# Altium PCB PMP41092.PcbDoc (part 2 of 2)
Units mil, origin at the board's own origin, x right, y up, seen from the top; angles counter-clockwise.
Board outline 1771.65 x 1771.65 mil, 6 copper layers (Top Layer 1, Layer 2, Layer 3, Layer 4, Layer 5, Bottom Layer), stack 32.112 mil thick; 119 components, 63 nets, 374 pads, 304 vias.
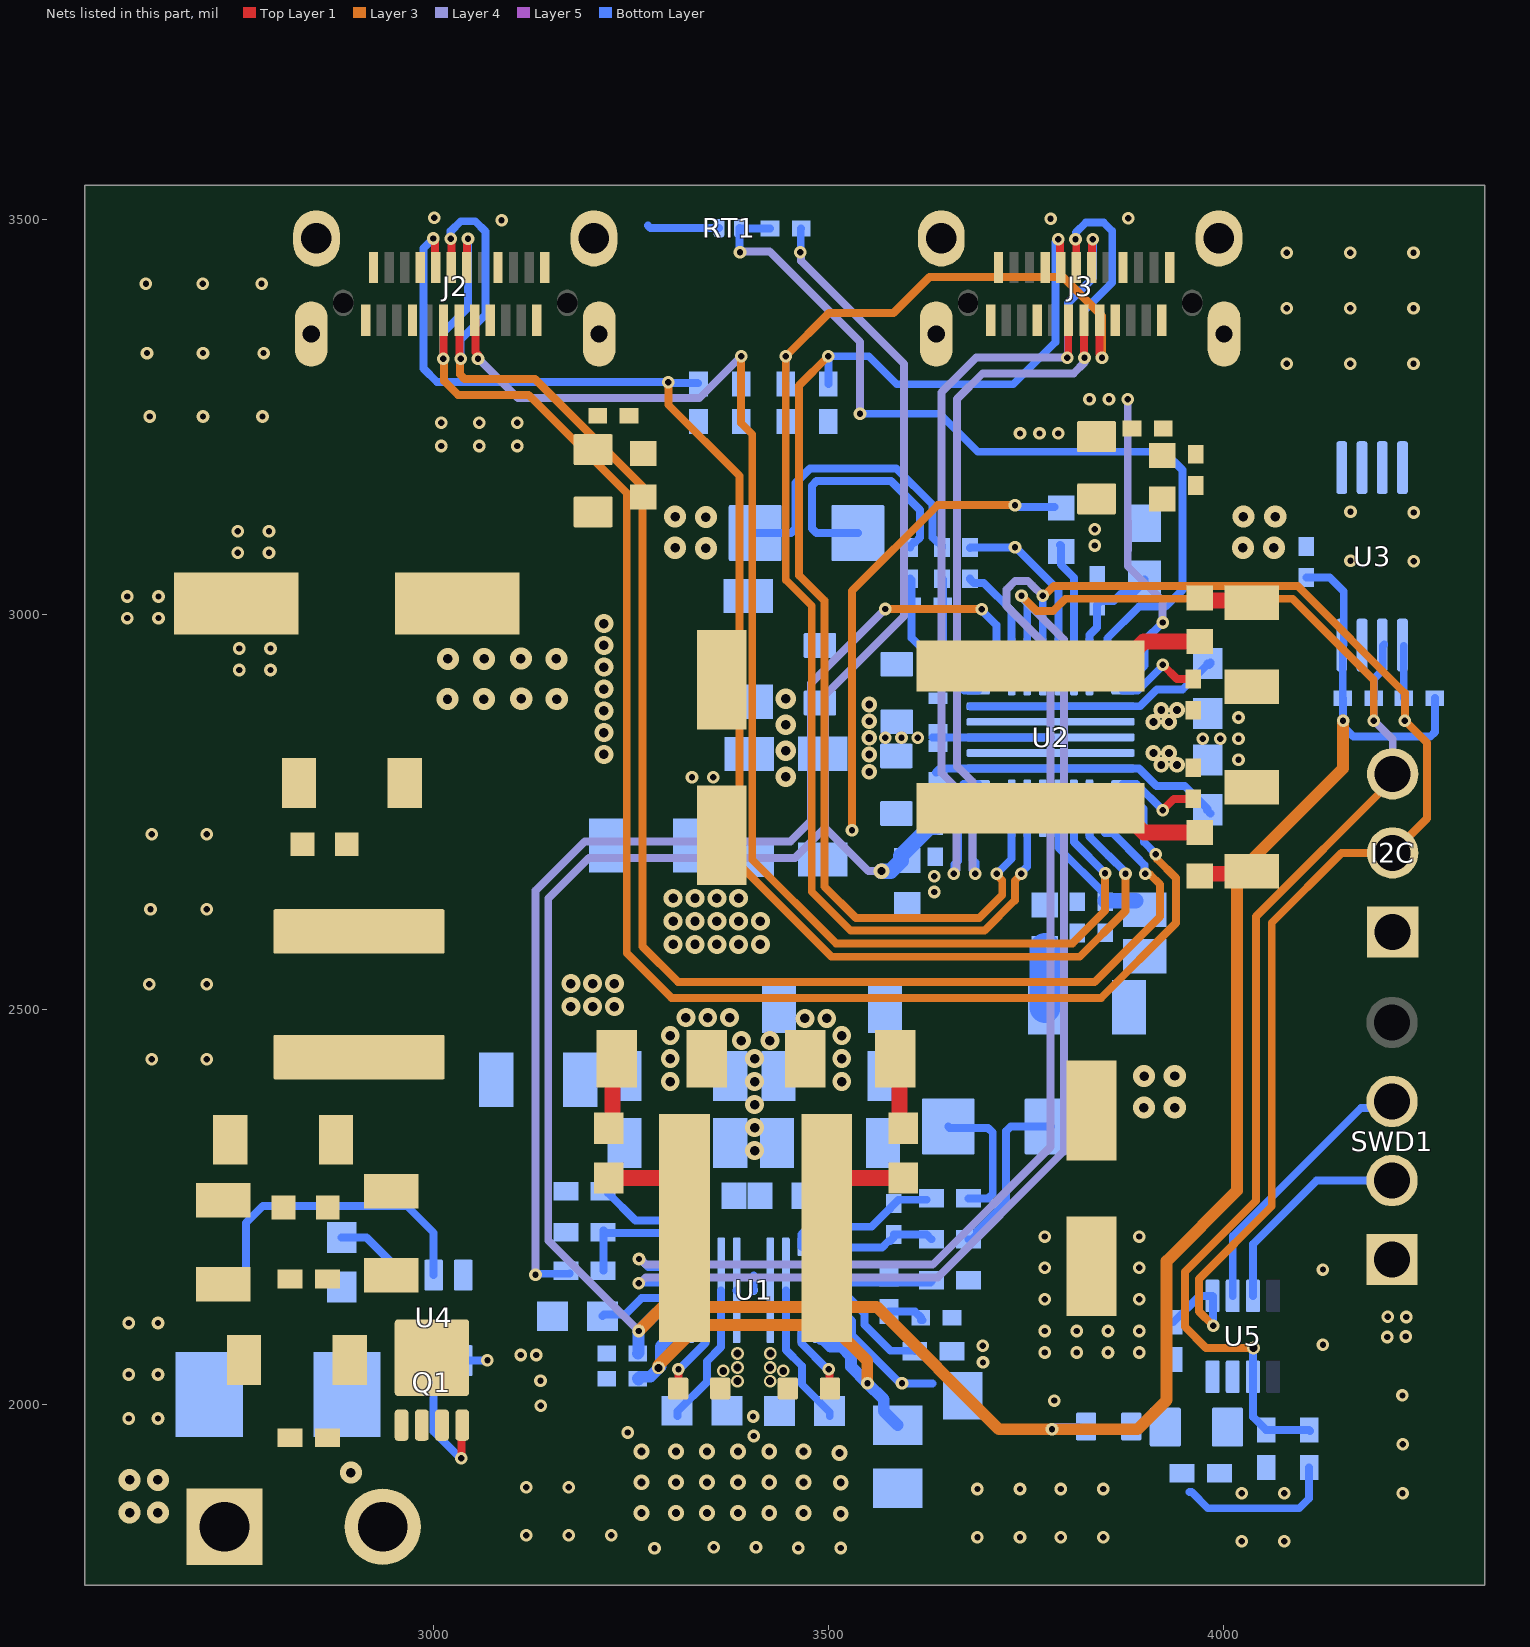
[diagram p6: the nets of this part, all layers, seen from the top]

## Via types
v1: diameter 16, hole 8, Top Layer 1 to Bottom Layer, tented top, 181 vias
v2: diameter 24, hole 12, Top Layer 1 to Bottom Layer, tented top, 45 vias
v3: diameter 20, hole 10, Top Layer 1 to Bottom Layer, tented top, 34 vias
v4: diameter 28, hole 12, Top Layer 1 to Bottom Layer, 25 vias
v5: diameter 16, hole 10, Top Layer 1 to Bottom Layer, tented top, 8 vias
v6: diameter 16, hole 8, Top Layer 1 to Bottom Layer, tented both sides, 4 vias
v7: diameter 26, hole 12, Top Layer 1 to Bottom Layer, tented top, 4 vias
v8: diameter 16, hole 10, Top Layer 1 to Bottom Layer, tented both sides, 2 vias
v9: diameter 20, hole 10, Top Layer 1 to Bottom Layer, tented both sides, 1 vias

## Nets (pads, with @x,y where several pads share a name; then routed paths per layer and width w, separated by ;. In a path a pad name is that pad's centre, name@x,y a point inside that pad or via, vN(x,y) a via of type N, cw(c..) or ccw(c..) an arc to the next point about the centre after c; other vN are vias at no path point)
3V3_MCU: C20.1 C27.2 R11.2 R12.2 R13.2 U5.4 | length 204.3
  Bottom Layer w10: 3956.99,1889.99 3959.39,1889.99 3980.14,1869.24 4095.86,1869.24 4108.41,1881.79 R13.2@4108.41,1920.9
AGND: C30.2 C31.2 C32.2 NT1.1 R7.1 R8.2 R9.1 U1.17 | length 179.2
  Bottom Layer w10: U1.17@3499.81,2115.44 3499.89,2115.36 3520.64,2115.36 3529.81,2106.19 3529.81,2088.19 3587.47,2030.53 3588.57,2030.53 3592.19,2026.91 3631.76,2026.91
  other v1: 3593.2,2027.53 3695.62,2053.72 3110.76,2063.14 3130.55,2063.14 3695.57,2074.82
AGND1: C59.2 C60.2 C63.2 C64.2 NT2.2 R22.1 U2.5 | length 231.5
  Bottom Layer w10: R22.1@3679.22,3084.24 3679.89,3084.91 3736.7,3084.91 3736.92,3085.12 3791.04,3031 U2.5@3791.04,2934.08
  other v1: 3736.1,3085.12 3837,3087.39 3837,3108
  other v6: 3634,2649 3634,2669
BATGND: C1.2 C2.2 C71.2 D1.1 J1.1 L4.1 U4.2 | length 377.9
  Bottom Layer w10: 2763.51,2166.67 2763.04,2167.14 2763.04,2230.18 2784.66,2251.8 2966.54,2251.8 3000.68,2217.66 U4.2@3000.68,2164.2
  other v1: 2614.89,1982.83 2651.86,1982.83 2614.89,2038.52 2651.86,2038.52 2614.89,2103.69 2651.86,2103.69
  other v4: 2615.98,1863.65 2651.81,1863.65 2615.98,1905.06 2651.81,1905.06
BOOT1: C41.1 U2.16 | length 108.8
  Top Layer 1 w10: v1(3923,2752.54) 3937.24,2766.78 C41.1@3961.99,2766.78
  Bottom Layer w10: U2.16@3872.73,2785.46 3872.81,2785.38 3890.16,2785.38 v1(3923,2752.54)
BOOT2: C42.1 U2.10 | length 112.4
  Top Layer 1 w10: v1(3923,2936.49) 3941.11,2918.38 C42.1@3961.99,2918.38 ; C42.1@3958.97,2920.36 C42.1@3959.82,2919.51
  Bottom Layer w10: U2.10@3872.73,2903.57 3872.81,2903.65 3891.54,2903.65 3923,2935.1 v1(3923,2936.49)
COMP: C31.1 R10.2 U1.15 | length 130
  Bottom Layer w10: U1.15@3499.81,2154.81 R10.2@3575.55,2154.81 ; R10.2@3576.64,2154.81 3629.03,2154.81 C31.1@3630.35,2156.13
EN_UVLO: R16.1 U2.6 | length 161.3
  Bottom Layer w10: R16.1@3793.32,3088.06 3794.16,3087.22 3794.16,3063.17 3810.8,3046.53 3810.8,2934.16 U2.6@3810.73,2934.08
FSW: R7.2 U1.6 | length 158.9
  Bottom Layer w10: R7.2@3220.96,2268.33 3256.05,2233.25 3323.34,2233.25 3344.7,2211.89 U1.6@3344.7,2200.08
GND: C3.2 C4.2 C5.2 C6.2 C7.2 C8.2 C9.2 C10.2 C11.2 C16.2 C17.2 C18.2 C19.2 C20.2 C21.2 C22.2 C23.2 C24.2 C25.2 C26.2 C27.1 C28.2 C35.2 C36.1 C37.2 C38.2 C39.1 C40.2 C43.2 C44.2 C47.2 C48.1 C50.1 C51.2 C53.1 C54.2 C55.1 C58.1 C61.2 C62.2 C65.1 C66.2 C67.2 C68.2 C69.2 I2C.1 J2.A1 J2.A12 J2.B1 J2.B12 J2.Shell J3.A1 J3.A12 J3.B1 J3.B12 J3.Shell L4.2 NT1.2 NT2.1 R1.2 R2.2 R15.1 R17.2 R23.1 RT1.1 SWD1.1 U1.9 U2.13 U3.1 U3.2 U3.3 U3.4 U3.7 U5.3 | length 259.6
  Bottom Layer w10: 3271.65,3492.13 3274.84,3488.94 RT1.1@3361.77,3488.94 ; U1.9@3405.69,2144.97 3405.69,2163.96 ; 3631.99,2844.51 U2.13@3781.2,2844.51
  other v1: 3279.99,1818.73 3461.97,1818.9 3515.75,1818.9 3355.02,1819.72 3408.44,1819.72 4022.88,1827.45 4076.66,1827.45 3688.64,1832.69 3742.43,1832.69 3793.96,1832.69 3847.74,1832.69 3117.77,1835.15 3171.55,1835.15 3225.33,1835.15 4022.88,1888.24 4076.66,1888.24 4226.58,1888.17 3688.64,1893.49 3742.43,1893.49 3793.96,1893.49 3847.74,1893.49 3117.77,1895.95 3171.55,1895.95 4226.75,1950.07 3405.51,1960.63 3246.22,1965.03 3404.79,1985.32 3136.21,1998.96 3785.8,2005.44 4226.38,2011.96 3135.91,2030.52 3773.86,2066.27 3814.13,2066.27 3853.83,2066.27 3893.24,2066.27 4125.79,2076.27 4207.31,2085.81 4230.57,2086.44 3773.86,2093.56 3814.13,2093.56 3853.83,2093.56 3893.24,2093.56 4231.12,2111.15 4207.7,2111.53 3773.86,2133.83 3893.24,2133.83 4125.79,2171.18 3773.86,2173.53 3893.24,2173.53 3773.86,2212.94 3893.24,2212.94 2643.78,2437.17 2713.45,2437.17 2640.81,2532.09 2713.45,2532.09 2642.29,2627 2713.45,2627 2643.78,2721.91 2713.45,2721.91 3327.54,2794.18 3354.59,2794.29 4019,2816.26 3973.67,2842.74 3996,2843 4019,2843 3572.16,2844 3592.58,2844 3613,2844 4019,2869.74 2754.82,2929.75 2794.24,2929.75 2754.82,2957.04 2794.24,2957.04 2613.02,2995.5 2652.44,2995.5 2613.02,3022.79 2652.44,3022.79 4240.83,3067.22 4160.67,3068.12 2752.94,3078.13 2792.36,3078.13 2752.94,3105.42 2792.36,3105.42 4240.83,3129.12 4160.67,3130.01 2641.6,3250.64 2708.87,3250.64 2784.03,3250.64 4080.11,3317.35 4160.27,3317.35 4240.43,3317.35 2638.02,3330.8 2708.88,3330.8 2785.46,3330.8 4080.11,3387.59 4160.27,3387.59 4240.43,3387.59 2636.57,3418.44 2708.66,3418.44 2782.93,3418.44 4080.11,3457.84 4160.27,3457.84
  other v2: 3406.75,2321.78 3406.75,2350.88 3406.75,2379.99 3300,2409.09 3406.75,2409.09 3517,2409.09 3300,2438.2 3406.75,2438.2 3517,2438.2 3390,2461 3426,2461 3300,2467.3 3517,2467.3 3470.44,2489 3498,2489 3319.87,2490 3347.44,2490 3375,2490 3174.31,2503.89 3201.87,2503.89 3229.44,2503.89 3174.31,2533 3201.87,2533 3229.44,2533 3303.75,2582.79 3331.31,2582.79 3358.87,2582.79 3386.44,2582.79 3414,2582.79 3303.75,2611.89 3331.31,2611.89 3358.87,2611.89 3386.44,2611.89 3414,2611.89 3303.75,2641 3331.31,2641 3358.87,2641 3386.44,2641 3216,2823.06 3216,2850.62 3216,2878.19 3216,2905.75 3216,2933.31 3216,2960.87 3216,2988.44
  other v3: 3515.75,1862.2 3263.78,1863.03 3307.09,1863.03 3346.46,1863.03 3385.83,1863.03 3425.2,1863.03 3468.5,1863.03 3263.78,1901.99 3307.09,1901.99 3346.46,1901.99 3385.83,1901.99 3425.2,1901.99 3468.5,1901.99 3515.75,1901.57 3514.04,1939.26 3263.78,1940.94 3307.09,1940.94 3346.46,1940.94 3385.83,1940.94 3425.2,1940.94 3468.5,1940.94 3551.74,2801 3551.74,2823 3551.74,2844 3551.74,2865 3551.74,2886
  other v6: 4240.43,3457.84
  other v7: 3446.26,2794.76 3446.26,2827.74 3446.26,2860.71 3446.26,2893.68
I2C1_SCL: C35.1 I2C.3 R13.1 R25.1 U1.3 U2.3 U3.6 U5.2 | length 3286.2
  Layer 3 w10: v1(3744.46,3023.61) 3763.49,3004.61 3784.61,3004.61 3800,3020 4087.37,3020 4190.11,2917.27 v1(4190.11,2865.79) ; v8(4038,2072) 3978,2072 3951.14,2098.86 3951.14,2168.4 4041,2258.26 4041,2618 4214,2791 I2C.3@4214,2798.35
  Layer 4 w10: v1(3260.15,2153.76) 3261.35,2153.76 3269.01,2161.42 3638.66,2161.42 3798,2320.75 3798,2968.45 3744.46,3021.99 v1(3744.46,3023.61) ; v1(4190.11,2865.79) 4214.09,2841.8 4214.09,2798.45 I2C.3@4214,2798.35
  Bottom Layer w10: v1(3260.15,2153.76) 3261.12,2154.73 3310.76,2154.73 U1.3@3310.84,2154.81 ; v1@3741.66,3024.79 v1@3742.84,3023.61 ; v1(3744.46,3023.61) v1@3742.84,3023.61 ; U2.3@3751.67,2934.08 3751.67,3014.78 v1@3742.84,3023.61 ; v8(4038,2072) 4037.29,2071.29 U5.2@4037.29,2035.52 4037.29,1984.86 C35.1@4054.01,1968.14 R13.1@4108.41,1968.14 R13.1@4109.45,1967.09 ; v1(4190.11,2865.79) 4190.11,2893.76 R25.1@4190.26,2893.91 4190.26,2918.47 4201.49,2929.7 4201.49,2960.34 U3.6@4203.38,2962.23
I2C1_SDA: I2C.2 R12.1 R26.1 U1.4 U2.4 U3.5 U5.5 | length 3208.9
  Layer 3 w10: v1(3771.36,3023.61) 3772.98,3023.61 3785.37,3036 4094,3036 4229.47,2900.53 v1(4229.47,2865.79) 4257.48,2837.78 4257.48,2741.83 I2C.2@4214,2698.35 4149.35,2698.35 4061,2610 4061,2251.39 3969,2159.39 3969,2118 v1(3987,2100)
  Layer 4 w10: v1(3260.45,2184.51) 3262.07,2184.51 3269.17,2177.42 3632.04,2177.42 3781,2326.38 3781,2955.22 3725.43,3010.79 3725.43,3031.51 3736.56,3042.64 3752.3,3042.64 3758.16,3036.78 v1(3771.36,3023.61) v1@3771.36,3021.97
  Bottom Layer w10: v1(3260.45,2184.51) 3262.07,2184.51 3272.1,2174.49 U1.4@3310.84,2174.49 ; U2.4@3771.36,2934.08 v1@3771.36,3021.97 ; R12.1@3936.37,2104.49 3969.76,2137.88 U5.5@3986.11,2137.88 3986.55,2137.43 3986.55,2100.45 v1(3987,2100) ; U3.5@4228.11,2960.16 R26.1@4228.11,2894.27 4229.47,2892.91 v1(4229.47,2865.79)
IN: C5.1 C6.1 C7.1 L2.2 L6.1 L9.1
  other v4: 3018.17,2893.05 3064.12,2893.05 3111.4,2893.39 3156.32,2893.05 3018.6,2943.92 3064.55,2943.92 3110.96,2944.26 3155.88,2943.92
IRQ1: R22.2 U2.2 | length 140.5
  Bottom Layer w10: R22.2@3679.22,3045.33 3679.22,3044.76 3684.06,3039.92 3696.68,3039.92 3731.99,3004.61 U2.2@3731.99,2934.08
ISN: C29.1 R6.2 U1.13 | length 154.4
  Bottom Layer w10: U1.13@3485.64,2199.1 3568.06,2199.1 3575.95,2206.99 3577.92,2206.99 3582.76,2211.83 C29.1@3582.76,2213.8 ; C29.1@3582.76,2215.48 3624.43,2215.48 R6.2@3630.35,2209.56
ISP: C29.2 R4.2 U1.12 | length 192.3
  Bottom Layer w10: U1.12@3465.96,2200.08 3465.96,2215.55 3475.75,2225.34 3554.57,2225.34 3577.27,2248.04 3577.92,2248.04 3578.34,2248.46 3578.34,2249.11 3588.78,2259.55 R4.2@3624.2,2259.55
LDO_1V5: C63.1 C64.1 U2.7 | length 157.3
  Bottom Layer w10: U2.7@3830.41,2934.08 3830.49,2934.16 3830.49,2973.99 3840,2983.5 C64.1@3840,3010.32 3840,3012.28 3844.84,3017.13 3861.16,3017.13 3869.98,3025.94 3884.33,3025.94 3900,3041.61 C63.1@3900,3044.57
LDO_3V3: C28.1 C59.1 C60.1 C65.2 R11.1 R24.2 R25.2 R26.2 U1.1 U2.27 U3.8 | length 4332.3
  Layer 3 w15: v1(3260.15,2093.49) 3290.66,2124 3561.04,2124 3715.83,1969.21 v1(3782.97,1969.21) 3891.21,1969.21 3928,2006 3928,2182 4017,2271 4017,2671 4151.3,2805.3 v1(4151.3,2865.79)
  Layer 4 w10: v1(3260.15,2093.49) 3145.59,2208.05 3145.59,2640.59 3197,2692 3457.58,2692 3495.78,2730.2 ; v1(3464.51,3458.42) 3465.66,3457.28 3465.66,3447.34 3596,3317 3596,2998 3495.78,2897.78 3495.78,2730.2 ; v9(3567.28,2675.28) 3550.7,2675.28 3495.78,2730.2
  Bottom Layer w10: v1(3464.51,3458.42) 3465.07,3458.98 3465.07,3487.85 R24.2@3465.62,3488.4 ; C59.1@3639.95,2737.84 3639.95,2754.42 3670.91,2785.38 3689.58,2785.38 U2.27@3689.66,2785.46 ; C65.2@4104.8,3046.76 4134.45,3046.76 4152.18,3029.03 4152.18,2962.24 4150.89,2960.92 R25.2@4150.89,2893.91 4151.3,2893.5 v1(4151.3,2865.79) ; 4152.45,2857.41 4164.41,2845.44 4261.62,2845.44 4267.48,2851.3 R26.2@4267.48,2894.27
  Bottom Layer w15: C28.1@3259,2065 3259.96,2065.96 3259.96,2093.3 v1(3260.15,2093.49) ; v1@3261.31,2095.11 3281.64,2115.44 U1.1@3310.84,2115.44 ; v1(3782.97,1969.21) 3783.16,1969.4 3813.43,1969.4 3813.65,1969.62 R11.1@3817.31,1969.62 ; 4151.3,2857.41 v1(4151.3,2865.79)
  Bottom Layer w20: v9(3567.28,2675.28) 3578.72,2675.28 3592,2688.56 3592,2694.8 3628.39,2731.18 3634.95,2731.18 3635.11,2731.34 C59.1@3635.11,2733
LDO_5V: C61.1 C62.1 U2.21 | length 180.1
  Bottom Layer w10: U2.21@3791.04,2754.95 3791.04,2705 3850.39,2645.65 C61.1@3850.39,2637.8
  Bottom Layer w20: C61.1@3850.39,2637.8 C62.1@3888.73,2637.8
MODE: R8.1 U1.2 | length 106.1
  Bottom Layer w10: R8.1@3214.21,2112.29 3216.25,2114.33 3243.04,2114.33 3263.84,2135.12 U1.2@3310.84,2135.12
NetC1_1: C1.1 C2.1 L3.1 Q1.5 Q1.6 Q1.7 Q1.8 Q1.9@2998.45,2059.73 U4.4 | length 39.9
  Top Layer 1 w10: Q1.9@2991.6,2060.29 Q1.9@2998.06,2053.82
  Bottom Layer w10: U4.4@3038.08,2055.93 3038.54,2056.39 v1(3068.67,2056.39)
NetC3_1: C3.1 C4.1 L2.1 L3.2
NetC8_1: C8.1 C9.1 C10.1 C11.1 L6.2 U1.7 | length 182.1
  Bottom Layer w10: C11.1@3309.19,1985.7 3309.19,1991.91 3346.35,2029.07 3346.35,2055.14 3364.3,2073.1 3364.3,2144.89 U1.7@3364.38,2144.97
NetC12_1: C12.1 R1.1 | length 92.2
  Top Layer 1 w20: C12.1@3222,2349.99 3227.1,2355.09 3227.1,2432.9 R1.1@3232.2,2438
NetC12_2: C12.2 C14.2 L7.1 U1.8 | length 146.2
  Top Layer 1 w20: C12.2@3222,2287 3295.95,2287 3318.04,2264.91 L7.1@3318.04,2224
  Bottom Layer w10: U1.8@3383.99,2144.89 U1.8@3384.07,2144.97
  other v5: 3385,2030 3367,2043 3385,2047.28 3385,2065
NetC13_1: C13.1 C15.2 L7.2 U1.10 | length 147.1
  Top Layer 1 w20: L7.2@3497.96,2224 3497.96,2264.91 3520.05,2287 C13.1@3595,2287
  other v5: 3426.3,2030 3443,2043 3426.3,2047.28 3426.6,2065
NetC13_2: C13.2 R2.1 | length 92.2
  Top Layer 1 w20: R2.1@3584.8,2438 3589.9,2432.9 3589.9,2355.09 C13.2@3595,2349.99
NetC14_1: C14.1 U1.20 | length 85
  Top Layer 1 w10: C14.1@3310.01,2020.61 3310.32,2020.93 v1(3310.32,2044.9) v1@3310.95,2045.53
  Bottom Layer w10: v1(3310.32,2044.9) 3311.2,2044.9 3344.7,2078.4 U1.20@3344.7,2089.85
NetC15_1: C15.1 U1.19 | length 86.2
  Top Layer 1 w10: v1(3500.69,2044.9) 3501.32,2044.27 3501.32,2020.13 C15.1@3501.95,2019.5
  Bottom Layer w10: U1.19@3465.96,2089.85 3465.96,2078.04 3499.09,2044.9 v1(3500.69,2044.9)
NetC16_1: C16.1 C17.1 C18.1 C19.1 C44.1 R3.1 R4.1 U1.11 | length 352.1
  Bottom Layer w10: U1.11@3446.27,2144.97 3446.35,2144.89 3446.35,2069.52 3466.47,2049.4 3466.47,2026.07 3501.85,1990.69 C16.1@3501.85,1985.64 ; R3.1@3651.71,2352.25 3653.56,2350.39 3702.14,2350.39 3708,2344.54 3708,2267.09 3702.14,2261.23 R4.1@3677.6,2261.23
NetC21_1: C21.1 C23.1 C24.1 FB1.1 R3.2 R6.1 | length 217.8
  Bottom Layer w10: R6.1@3677.6,2209.56 3681.53,2209.56 3688.34,2216.37 3688.34,2220.31 3725,2256.96 3725,2346.39 3730.86,2352.25 R3.2@3781.63,2352.25
  other v4: 3899.23,2376.22 3938.27,2376.22 3899.62,2416.05 3938.27,2416.11 4024.47,3084.43 4063.7,3084.43 4025.14,3123.84 4065.43,3123.84
NetC30_1: C30.1 R5.1 U1.5 | length 174.6
  Bottom Layer w10: R5.1@3215.74,2169.68 3215.45,2169.97 3215.45,2221.01 3219.21,2217.25 3314.58,2217.25 3325.01,2206.82 U1.5@3325.01,2199.1
NetC32_1: C32.1 R10.1 | length 45.6
  Bottom Layer w10: R10.1@3576.68,2118.09 3609.49,2118.09 C32.1@3617.12,2110.46 ; C32.1@3617.12,2107.02 C32.1@3619.15,2107.02
NetC33_2: C33.2 R15.2 | length 68.4
  Top Layer 1 w20: C33.2@3970,2669.13 3972.95,2672.09 4033.05,2672.09 R15.2@4036,2675.04
NetC34_2: C34.2 R17.1 | length 76.9
  Top Layer 1 w20: C34.2@3970,3020.87 3972.95,3017.91 4037.19,3017.91 R17.1@4043.16,3011.94
NetC43_1: C43.1 C47.1 FB2.1 R19.2 R20.2 | length 370.8
  Bottom Layer w10: R20.2@3407.45,3103.1 3452.65,3103.1 3458.51,3108.96 3458.51,3166.51 3476.84,3184.84 3585.92,3184.84 3632,3138.76 3632,3097.37 3637.86,3091.51 3639,3091.51 3643.84,3086.67 R19.2@3643.84,3084.7
  other v4: 3345.04,3083.88 3306.21,3084.53 3345.04,3123.35 3306.21,3124
NetC49_1: C49.1 R21.1 U2.28 | length 187.5
  Bottom Layer w10: R21.1@3603.71,3045.33 3605.49,3043.55 C49.1@3605.49,3011.76 3605.49,2970.4 3672.32,2903.57 U2.28@3689.66,2903.57
NetC49_2: C49.2 R19.1 U2.29 | length 148.5
  Bottom Layer w10: R19.1@3643.84,3045.33 3644.86,3044.31 C49.2@3644.86,3011.76 3644.86,2953.65 3675.26,2923.25 U2.29@3688.68,2923.25
NetC50_2: C50.2 C51.1 C53.2 C54.1 C55.2 R20.1 R21.2 U2.11 | length 649.2
  Bottom Layer w10: R20.1@3537.37,3103.1 3485.06,3103.1 3479.2,3108.96 3479.2,3162.98 3485.06,3168.84 3579.29,3168.84 3616,3132.13 3616,3097.37 3610.14,3091.51 3608.55,3091.51 3603.71,3086.67 R21.2@3603.71,3084.7 ; U2.11@3679.98,2883.88 U2.11@3781.2,2883.88 3781.28,2883.96 3894.49,2883.96 3915.91,2905.38 3948.37,2905.38 3980,2937.01 C51.1@3980,2937.99 ; C51.1@3981.81,2936.19 3983.71,2938.09 C51.1@3983.71,2939.07
NetC57_2: C57.2 R23.2 | length 74.4
  Bottom Layer w39.37: R23.2@3774,2503 C57.2@3774.02,2577.36
NetC72_1: C72.1 U4.1 | length 98.8
  Bottom Layer w10: C72.1@2884.24,2211.91 2915.57,2211.91 U4.1@2963.28,2164.2
NetQ1_4: Q1.4 U4.5 | length 180.9
  Top Layer 1 w10: v1(3035.72,1932.47) 3035.72,1973.18 Q1.4@3036.84,1974.29
  Bottom Layer w10: U4.5@3000.68,2055.93 3000.68,1966.38 3034.59,1932.47 v1(3035.72,1932.47)
NetR9_2: R9.2 U1.16 | length 145.7
  Bottom Layer w10: U1.16@3499.81,2135.12 3526.31,2135.12 3545.81,2115.62 3545.81,2101.36 3578.63,2068.54 3608.84,2068.54 R9.2@3609.38,2068
NTC: R24.1 RT1.2 U2.8 | length 1096
  Layer 4 w10: v1(3388.32,3458.42) 3389.47,3459.57 3425.43,3459.57 3540,3345 v1(3540,3254)
  Bottom Layer w10: v1(3388.32,3458.42) 3387.36,3459.39 RT1.2@3387.36,3488.94 3387.89,3488.4 R24.1@3426.25,3488.4 ; v1(3540,3254) 3641,3254 3689,3206 3925,3206 3948,3183 3948,3031.16 3926.78,3009.94 3893.07,3009.94 3852.99,2969.86 U2.8@3852.99,2944.11
PA_CC1: C66.1 J2.A5 U2.20 | length 1756.9
  Top Layer 1 w10: J2.A5@3052.51,3372.28 3053.42,3371.38 3053.42,3332.06 3056.74,3328.74 v1@3056.74,3324.23
  Layer 3 w10: v1(3389.76,3326.77) 3389.76,3242.11 3403.78,3228.09 3403.78,2689.84 3509.63,2584 3809,2584 3850.17,2625.17 v1(3850.17,2672.74)
  Layer 4 w10: v1@3056.74,3324.23 3107.23,3273.74 3336.73,3273.74 v1(3389.76,3326.77)
  Bottom Layer w10: C66.1@3389.76,3291.67 v1(3389.76,3326.77) ; U2.20@3810.73,2754.95 3810.73,2712.19 v1(3850.17,2672.74)
  other v1: 3056.74,3323.67
PA_CC2: C67.1 J2.B5 U2.19 | length 1921
  Top Layer 1 w10: v1(3000.1,3475.74) 3000.1,3474.12 3002.4,3471.83 3002.4,3440.12 J2.B5@3003.3,3439.21
  Layer 3 w10: v1(3297.6,3293.97) 3297.6,3265.4 3387.78,3175.22 3387.78,2683.22 3504,2567 3818,2567 3876,2625 v1(3876,2672)
  Bottom Layer w10: v1(3000.1,3475.74) 2987.8,3463.45 2987.8,3311.2 3005.03,3293.97 v1(3297.6,3293.97) ; v1@3295.24,3292.74 3334.72,3292.74 C67.1@3334.89,3292.56 ; U2.19@3830.41,2754.95 3830.41,2718.89 3854.1,2695.2 3854.59,2695.2 3876,2673.78 v1@3876,2672.74
PA_D_N: J2.A7 J2.B7 U2.17 | length 2099.5
  Top Layer 1 w10: v1(3012.74,3323.67) 3013.15,3324.08 3013.15,3357.6 3012.83,3357.92 J2.A7@3012.83,3371.97 ; J2.B7@3042.99,3439.53 3042.99,3474.5 v1(3044.1,3475.61)
  Layer 3 w10: v1(3012.74,3323.67) 3013.89,3322.52 3013.89,3312.2 3013.89,3295.57 3031.46,3278 3120.72,3278 3245,3153.72 3245,2571.72 3301.72,2515 3845.28,2515 3939.85,2609.56 3939.85,2666.61 3915.53,2690.93 3915.53,2695.73 v1(3914.38,2696.88)
  Bottom Layer w10: v1(3012.74,3323.67) 3012.74,3356.93 3044.1,3388.29 v1(3044.1,3475.61) ; U2.17@3873.72,2765.77 3887.14,2765.77 3899.09,2753.82 3899.09,2712.37 3914.38,2697.08 v1(3914.38,2696.88)
PA_D_P: J2.A6 J2.B6 U2.18 | length 2068.2
  Top Layer 1 w10: v1@3022.1,3476.79 3022.99,3475.91 J2.B6@3022.99,3439.21 ; J2.A6@3032.83,3372.28 3033.15,3371.96 v1@3033.15,3325.02 ; v1@3033.59,3325.02 v1@3034.74,3323.87
  Layer 3 w10: v1@3034.74,3323.87 3033.89,3323.02 3033.89,3303.86 3039.75,3298 3129,3298 3265,3162 3265,2580 3310,2535 3837,2535 3919.85,2617.85 3919.85,2658.32 3907.32,2670.85 3902.15,2670.85 v1(3901,2672)
  Bottom Layer w10: v1(3022.1,3475.61) 3022.1,3485.19 3022.56,3485.19 3034.99,3497.61 3053.21,3497.61 3066.1,3484.73 3066.1,3379.18 3034.74,3347.82 v1@3034.74,3323.87 ; 3850.13,2723.72 3859.65,2723.72 3879.09,2704.29 3879.09,2704.09 3894.38,2688.79 3894.38,2688.59 3899.85,2683.12 3899.85,2673.15 v1(3901,2672)
  other v1: 3034.74,3323.67
PA_VBUS: C48.2 FB2.2 J2.A4 J2.A9 J2.B4 J2.B9
  other v1: 3010.43,3213.31 3058.37,3213.31 3106.31,3213.31 3010.43,3242.45 3058.37,3242.45 3106.31,3242.45 3086.58,3498.74 3001.45,3502.01
PB_CC1: C68.1 J3.A5 U2.23 | length 1702.2
  Top Layer 1 w10: J3.A5@3843.21,3372.28 3843.21,3329.45 3846.22,3326.45 v1(3846.22,3324.82)
  Layer 3 w10: v1(3744,2672) 3744,2671.14 3736,2663.14 3736,2638.37 3697.63,2600 3528.37,2600 3479,2649.37 3479,3011 3446.08,3043.92 v1(3446.08,3326.77) 3500.81,3381.5 3582.5,3381.5 3628,3427 3797,3427 3846.22,3377.78 v1(3846.22,3324.82)
  Bottom Layer w10: C68.1@3446.08,3295.7 v1(3446.08,3326.77) ; v1(3744,2672) 3744,2673.62 3751.67,2681.29 U2.23@3751.67,2754.95
PB_CC2: C69.1 J3.B5 U2.24 | length 1596.3
  Top Layer 1 w10: v1@3793.09,3470.72 3793.09,3440.12 J3.B5@3794,3439.21
  Layer 3 w10: v1(3500,3326.77) 3463,3289.77 3463,3049.63 3495,3017.63 3495,2656 3535,2616 3691,2616 3720,2645 3720,2663.36 3712.98,2670.38 v1(3712.98,2672)
  Bottom Layer w10: C69.1@3500,3291.54 v1(3500,3326.77) 3551.16,3326.77 3586.61,3291.32 3733.99,3291.32 3787.2,3344.54 3787.2,3471.2 v1(3790.72,3474.72) ; v1(3712.98,2672) 3731.99,2691 U2.24@3731.99,2754.95
PB_D_N: J3.A7 J3.B7 U2.26 | length 1144.5
  Top Layer 1 w10: v1@3802.2,3324.57 3803.35,3325.72 3803.35,3329.96 3803.53,3330.13 J3.A7@3803.53,3371.97 ; J3.B7@3833.68,3453.3 3833.68,3473.68 v1(3834.72,3474.72)
  Layer 4 w10: v1(3658.7,2672) 3658.7,2673.62 3662.39,2677.31 3662.39,2780.28 3642.95,2799.72 3642.95,3281.03 3687.12,3325.2 v1@3802.2,3325.2
  Bottom Layer w10: v1(3658.7,2672) 3659.8,2673.1 3659.8,2684.05 3663.9,2688.15 3663.9,2754.41 3666.32,2756.83 3666.32,2758.16 3673.93,2765.77 U2.26@3688.68,2765.77 ; v1@3802.2,3324.57 3803.2,3325.57 3803.2,3394.18 3834.81,3425.79 3834.81,3474.63 v1(3834.72,3474.72)
  other v1: 3802.2,3324.82
PB_D_P: J3.A6 J3.B6 U2.25 | length 1196.1
  Top Layer 1 w10: v1(3812.72,3474.72) 3813.68,3473.75 J3.B6@3813.68,3439.21 ; v1@3823.53,3325.25 J3.A6@3823.53,3372.28
  Layer 4 w10: v1(3686.08,2672) 3686.08,2673.62 3682.39,2677.31 3682.39,2788.56 3662.95,2808.01 3662.95,3272.75 3695.4,3305.2 3810.49,3305.2 3824.2,3318.91 v1(3824.2,3324.82) v1@3824.2,3325.2
  Bottom Layer w10: 3683.03,2745.77 3682.21,2745.77 3682.21,2689.87 3686.08,2686 v1(3686.08,2672) ; U2.25@3710.95,2744.73 U2.25@3711.13,2744.92 ; v1(3812.72,3474.72) 3813.49,3475.48 3813.49,3483.55 3825.73,3495.79 3848.44,3495.79 3859.18,3485.06 3859.18,3420 3823.2,3384.03 3823.2,3325.57 v1@3823.87,3324.91
PB_VBUS: C22.1 FB1.2 J3.A4 J3.A9 J3.B4 J3.B9 U2.9 | length 396.4
  Layer 4 w10: v1(3878.82,3272.5) 3878.82,3118.05 3879,3117.87 3879,3081.53 3878.82,3081.34 3878.82,3061.18 3923,3017 v1(3923,2990)
  Bottom Layer w10: U2.9@3873.72,2923.25 3873.8,2923.33 3887.89,2923.33 3900,2935.45 3900,2967 v1(3923,2990)
  other v1: 3742.45,3229.14 3767.14,3229.14 3790.81,3229.14 3830.46,3272.44 3855.14,3272.5 3781.2,3500.73 3879.33,3501.3
SW1: C33.1 C41.2 L8.1 U2.14 | length 226.8
  Top Layer 1 w20: L8.1@3756,2755.04 3868.2,2755.04 3898.99,2724.25 C33.1@3970,2724.25
  other v3: 3921.2,2809.83 3941,2809.83 3911.2,2824.83 3931,2824.83
SW2: C34.1 C42.2 L8.2 U2.12 | length 226.8
  Top Layer 1 w20: L8.2@3756,2934.96 3868.2,2934.96 3898.99,2965.75 C34.1@3970,2965.75
  other v3: 3911.2,2864.2 3931,2864.2 3921.2,2879.2 3941,2879.2
SWCLK: SWD1.2 U5.7 | length 274.8
  Bottom Layer w10: U5.7@4037.29,2137.88 4037.29,2203.32 4117.84,2283.87 SWD1.2@4213.24,2283.87
SWDIO: SWD1.3 U5.6 | length 347.7
  Bottom Layer w10: U5.6@4011.7,2137.88 4011.7,2213.43 4174.12,2375.85 4205.22,2375.85 SWD1.3@4213.24,2383.87
SYNC: R5.2 U2.1 | length 1386.5
  Layer 3 w10: v1(3572,3007) 3693.88,3007 v1(3694.24,3006.64)
  Layer 4 w10: v1(3129.59,2164.83) 3129.59,2650.59 3192,2713 3452,2713 3478,2739 3478,2913 v1(3572,3007)
  Bottom Layer w10: v1@3132.45,2165.92 3172.62,2165.92 R5.2@3172.82,2166.12 ; v1(3694.24,3006.64) 3694.24,3005.01 3712.75,2986.5 3712.75,2968.39
TVSP: C57.1 C58.2 U2.22
VBAT: C71.1 C72.2 D1.2 J1.2 Q1.1 Q1.2 Q1.3 U4.3 U4.6
  other v4: 2896,1914.42
VCC: C25.1 C26.1 U1.18 U1.21 | length 610.4
  Layer 5 w15: v8(3285.12,2046.83) v8@3285.12,2047.1 ; v6@3549.25,2027.48 v6(3549.52,2027.48)
  Layer 3 w15: v8(3285.12,2046.83) 3285.12,2050.1 3336.02,2101 3504,2101 3549.33,2055.67 3549.33,2027.67 v6(3549.52,2027.48)
  Bottom Layer w15: C25.1@3260,2032.17 C25.1@3259,2033.17 3261.34,2035.51 3274.86,2035.51 3288,2048.66 3288,2074 3304,2090 3324.18,2090 U1.21@3325.01,2090.83 ; U1.18@3485.64,2090.83 3485.64,2088.11 3490.8,2082.96 3493.52,2082.96 3502.59,2073.89 3516.11,2073.89 3528.81,2061.19 3528.81,2048.19 ; 3529,2048 v6(3549.52,2027.48) 3570.04,2006.96 3570.04,1992.21 C26.1@3587.9,1974.35
VIN: C36.2 C37.1 C38.1 C39.2 C40.1 L9.2 R16.2 U2.15 | length 979.3
  Layer 3 w10: v1(3530,2727) 3530,3030.02 3638.38,3138.4 v1(3736.1,3138.4)
  Bottom Layer w10: C39.2@3636.15,2800.04 3641.25,2805.14 U2.15@3781.2,2805.14 3781.28,2805.06 3893.1,2805.06 3915.15,2783.01 3950.95,2783.01 3979.93,2754.03 C40.1@3979.93,2753.04 ; v1(3736.1,3138.4) 3737.73,3138.4 3740.15,3135.98 R16.2@3786.12,3135.98 ; C40.1@3979.29,2752.4 C40.1@3983.64,2748.04
pads on no net: J2.A2 J2.A3 J2.A8 J2.A10 J2.A11 J2.B2 J2.B3 J2.B8 J2.B10 J2.B11 J2.M1 J2.M2 J3.A2 J3.A3 J3.A8 J3.A10 J3.A11 J3.B2 J3.B3 J3.B8 J3.B10 J3.B11 J3.M1 J3.M2 Q1. Q1.9@2998.45,2046.93 RT1.1S RT1.2S SWD1.4 U1.14 U5.1 U5.8

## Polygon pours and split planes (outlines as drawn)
VCC on Bottom Layer "VCC_L06_P204" (solid, remove dead copper, pour order 204): 3496,2105 3539,2062 3593,2008 3615,2008 3627,1996 3627,1953 3619,1945 3558,1945 3549,1954 3549,2005.47 3477.74,2076.73 3477.74,2100.08 3482.66,2105
NetC16_1 on Bottom Layer "NONET_L01_P-001" (solid, pour order 70): 3479.84,2038.56 3479.84,2045.16 3453.61,2071.38 3453.55,2076.72 3453.55,2093.14 3468.69,2108.28 3477.41,2108.28 3481.41,2112.27 3481.41,2178.3 3478.1,2181.61 3463,2181.61 3457.35,2187.26 3454.96,2187.26 3454.89,2187.33 3454.89,2217.43 3475.34,2237.88 3531.44,2237.88 3573.65,2280.08 3656.7,2280.08 3684.64,2308.01 3684.64,2522.82 3663.28,2544.17 3549.01,2544.17 3539.01,2534.17 3539.01,2339.66 3489.62,2290.27 3450.45,2290.27 3438.31,2278.13 3438.31,2238.96 3438.31,2172.94 3438.31,2069.85 3461.55,2046.61 3461.55,2024.03 3472.04,2013.54 3472.04,1970.8 3477.84,1965 3521,1965 3531.44,1975.44 3531.44,2006.56 3509.49,2028.51 3489.89,2028.51
AGND1 on Bottom Layer "AGND1_L06_P201" (solid, remove dead copper, pour order 201): 3577,2610 3577,2649.7 3582.99,2655.69 3603.11,2655.69 3612.61,2655.69 3623.23,2666.31 3623.23,2704.23 3624,2705 3625,2709 3646,2709 3649,2706 3649,2609 3644,2604 3583,2604
GND on Bottom Layer "NONET_L01_P-001" (solid, remove dead copper, pour order 202): 3078,2209 3091,2196 3091,1819.39 3124.46,1785.93 4256.79,1785.93 4304.44,1833.57 4304.44,3472.11 4257.91,3518.63 2663.23,3518.63 2585.69,3441.09 2585.69,2232.99 2609.5,2209
NetC12_2 on Bottom Layer "NONET_L01_P-001" (solid, pour order 157): 3353.07,2036.93 3375,2015 3388.47,2015 3394.23,2020.77 3394.23,2074.15 3389.58,2078.8 3389.58,2211.36 3376.24,2211.36 3376.24,2073.4 3353.07,2050.23
SW1 on Bottom Layer "NONET_L01_P-001" (solid, pour order 76): 3674.88,2828.26 3676.11,2829.49 3895.95,2829.49 3906.47,2840 3934.77,2840 3950,2824.77 3950,2800 3945,2795 3920.08,2795 3897.31,2817.76 3678.3,2817.76 3674.88,2821.18
LDO_1V5 on Bottom Layer "LDO_1V5_L06_P196" (solid, remove dead copper, pour order 196): 3824.61,2999.8 3880,3055.19 3880,3070 3920,3070 3930,3060 3930,3030 3920,3020 3875.52,3020 3846.75,2991.23 3846.75,2970.5 3824.61,2970.5
AGND1 on Bottom Layer "NONET_L01_P-001" (solid, pour order 156): 3827.21,3041.52 3827.21,3124.77 3845.05,3142.61 3917.39,3142.61 3929,3131 3929,3087.33 3918.74,3077.07 3870.47,3077.07 3864.06,3070.66 3864.06,3050.62 3847.75,3034.31 3834.42,3034.31
NetC50_2 on Bottom Layer "NONET_L01_P-001" (solid, pour order 112): 3894.1,2890.55 3913.55,2910 3938,2910 3955,2927 3955,2956 3964,2965 4001,2965 4007,2959 4007,2919 4001,2913 3966,2913 3952.89,2899.89 3919.36,2899.89 3897.46,2878 3622,2878 3585,2915 3367.1,2915 3348.33,2933.76 3348.33,3036.51 3365.38,3053.56 3477.36,3053.56 3496.09,3072.3 3496.09,3148.01 3507.09,3159.01 3571.51,3159.01 3584.06,3146.46 3584.06,2980.82 3674.33,2890.55
VIN on Bottom Layer "NONET_L01_P-001" (solid, pour order 111): 3551.18,2682.18 3667.03,2798.03 3893.1,2798.03 3923.56,2767.56 3945.44,2767.56 3956,2757 3955.5,2737.5 3962,2731 3999,2731 4002,2734 4002,2775 3997,2780 3966,2780 3957.21,2788.79 3916.72,2788.79 3893.1,2812.41 3621.41,2812.41 3597.79,2788.79 3550.45,2788.79 3530.99,2769.42 3305.23,2769.42 3296.63,2760.81 3296.63,2674.35 3309.98,2660.99 3515.14,2660.99 3529.99,2660.99
SW2 on Bottom Layer "NONET_L01_P-001" (solid, pour order 191): 3674.88,2860.77 3676.11,2859.54 3895.95,2859.54 3905.49,2850 3935.75,2850 3950,2864.25 3950,2890 3945.98,2894.02 3920.08,2894.02 3897.31,2871.26 3678.3,2871.26 3674.88,2867.84
NetC8_1 on Bottom Layer "C" (solid, pour order 79): 3230.24,2292.32 3234.93,2292.32 3239.66,2287.87 3239.66,2269.98 3264.67,2244.97 3293.67,2244.97 3301.66,2236.99 3329.46,2236.99 3356.74,2209.71 3356.74,2203.72 3352.05,2199.04 3346.39,2193.51 3346.39,2181.63 3346.37,2181.61 3333.62,2181.61 3330.46,2178.45 3330.46,2111.09 3333.23,2108.32 3347.83,2108.32 3356.74,2099.42 3356.74,2073.4 3372.42,2073.4 3372.42,2228.81 3353.2,2248.03 3353.2,2281.35 3343.86,2290.69 3313.23,2290.69 3277.02,2326.91 3277.02,2446.57 3263.29,2460.3 3171.63,2460.3 3163.72,2452.39 3163.72,2332.32 3203.72,2292.32
NetC8_1 on Bottom Layer "NONET_L01_P-001" (solid, pour order 174): 3344.92,2055.14 3346.35,2055.14 3346.35,2021.86 3337.66,2013.16 3337.66,1974.38 3328.13,1964.85 3289.35,1964.85 3279.21,1974.99 3279.21,2020.01 3286.18,2026.98 3316.75,2026.98
VBAT on Bottom Layer "NONET_L01_P-001" (solid, pour order 100): 3050.76,2185.88 3078.73,2157.91 3078.73,1833.23 3031.93,1786.43 2870.96,1786.43 2842.71,1814.68 2842.71,2161.54 2867.05,2185.88
NetC21_1 on Bottom Layer "NONET_L01_P-001" (solid, pour order 116): 3939.3,2446.93 3955.68,2430.55 3955.68,2322.14 3938.87,2305.59 3760.41,2305.59 3748,2318 3748,2429 3765.93,2446.93
NetC13_1 on Bottom Layer "NONET_L01_P-001" (solid, pour order 169): 3457.5,2037.18 3457.18,2037.18 3437.59,2017.59 3420.09,2017.59 3416.34,2021.34 3416.34,2079.94 3420.99,2084.59 3420.99,2211.44 3431.5,2211.44 3431.5,2084.37 3457.5,2058.37
NetC43_1 on Bottom Layer "NONET_L01_P-001" (solid, pour order 134): 3445.4,3070.22 3433.55,3058.36 3291.76,3058.36 3280.82,3069.3 3280.82,3136.19 3300.78,3156.15 3431.84,3156.15 3445.4,3142.59
TVSP on Bottom Layer "TVSP_L06_P173" (solid, pour order 173): 3820.52,2616.47 3755.7,2616.47 3752.19,2619.98 3752.19,2649.19 3763.25,2660.25 3763.25,2744.54 3778.03,2744.54 3778.03,2702.65 3827.59,2653.09 3827.59,2623.54
AGND on Bottom Layer "NONET_L01_P-001" (solid, pour order 90): 3188.14,2158.09 3188.14,2074.93 3162.13,2048.93 3108.63,2048.93 3083.92,2073.96 3083.93,2296.51 3105.55,2318.13 3169.59,2318.13 3188.14,2299.57
AGND on Bottom Layer "NONET_L01_P-001" (solid, pour order 89): 3611.78,2062.75 3611.78,2030.83 3626.2,2016.4 3694.64,2016.4 3708.62,2030.39 3708.62,2162.31 3698.32,2172.62 3658.35,2172.62 3652.58,2166.85 3652.58,2132.69 3640.44,2120.55 3640.44,2091.41
IN on Bottom Layer "NONET_L01_P-001" (solid, pour order 151): 3149.41,2982.32 3185.5,2946.44 3185.5,2826.64 3242.8,2769.34 3242.8,2671.75 3129.13,2558.08 3129.13,2369.37 3111,2351.25 3030.8,2351.25 3029.41,2349.86 3011.9,2367.37 3011.9,2831.68 2969.93,2873.65 2969.93,2950.59 3001.66,2982.32
3V3_MCU on Bottom Layer "NONET_L01_P-001" (solid, pour order 122): 3893.94,1898.55 3911.42,1881.07 3958.03,1881.07 3972.08,1895.12 3972.08,1990.74 3996.12,2014.78 3996.12,2055.12 3968.89,2082.35 3918.04,2082.35 3911.42,2075.73 3911.42,2030.02 3893.71,2012.31 3880.99,2012.31 3868.27,1999.59 3868.27,1958.06 3881.25,1945.08 3893.94,1932.38
BATGND on Bottom Layer "NONET_L01_P-001" (solid, pour order 102): 2808.73,2188.46 2834.55,2162.63 2834.55,1810.09 2806.56,1782.1 2611.78,1782.1 2584.1,1809.78 2584.1,2162.36 2610.2,2188.46
GND on Top Layer 1 "NONET_L01_P-001" (solid, remove dead copper, pour order 197): 3062,2209 3091,2180 3091,1819.39 3124.46,1785.93 4256.79,1785.93 4304.44,1833.57 4304.44,3472.11 4257.91,3518.63 2663.23,3518.63 2585.69,3441.09 2585.69,2232.99 2609.5,2209
SW2 on Top Layer 1 "NONET_L01_P-001" (solid, pour order 195): 3606,2905 3626,2885 3854,2885 3891.54,2847.46 3967.39,2847.46 3974.63,2854.7 3974.63,2892.42 3966.65,2900.39 3928.93,2900.39 3907.39,2921.94 3907.39,2964.61 3892,2980 3619,2980 3606,2967
NetC13_1 on Top Layer 1 "c" (solid, pour order 190): 3467,2371.95 3458,2362.95 3458,2123 3415,2080 3415,2016.83 3426,2005.83 3463.38,2005.83 3469.3,2011.75 3469.3,2039.3 3501,2071 3531,2071 3537,2077 3537,2364 3529.05,2371.95
NetC12_2 on Top Layer 1 "c" (solid, pour order 159): 3349,2371.95 3358,2362.95 3358,2123 3401,2080 3401,2016.83 3390,2005.83 3352.62,2005.83 3346.7,2011.75 3346.7,2039.3 3315,2071 3285,2071 3279,2077 3279,2364 3286.95,2371.95
PB_VBUS on Top Layer 1 "c" (solid, pour order 74): 3768.21,3464 3758,3474.21 3758,3505.37 3764.56,3511.93 3873.54,3511.93 3873.55,3511.92 3880.75,3511.92 3887.42,3505.25 3887.42,3487.7 3879.99,3480.18 3879.99,3410.55 3868.48,3399.05 3868.48,3317.76 3896.64,3289.6 3896.64,3207.51 3872.79,3183.66 3748.3,3183.66 3722.96,3209 3722.96,3282.69 3758.94,3318.67 3758.94,3391.82 3768.21,3401.09
NetC1_1 on Top Layer 1 "NONET_L01_P-001" (solid, pour order 80): 3022,2190 3082.73,2129.27 3082.73,2019.91 3067.86,2005.04 2862.54,2005.04 2848.34,2019.24 2848.34,2173.34 2865,2190
IN on Top Layer 1 "c" (solid, pour order 77): 2803.11,2677.1 2788.93,2662.92 2788.93,2566.18 2804.64,2552.5 3018.85,2552.5 3035.12,2568.78 3035.12,2681.38 3176.49,2822.75 3176.49,3010.72 3121.58,3065.63 2921.27,3065.63 2864.17,3008.53 2864.17,2692.07 2849.19,2677.1
SW1 on Top Layer 1 "NONET_L01_P-001" (solid, pour order 165): 3606,2785 3626,2805 3854,2805 3891.54,2842.54 3967.39,2842.54 3974.63,2835.3 3974.63,2797.58 3966.65,2789.61 3928.93,2789.61 3907.39,2768.06 3907.39,2725.39 3892,2710 3619,2710 3606,2723
NetC21_1 on Top Layer 1 "NONET_L01_P-001" (solid, pour order 107): 3944.67,2297.26 3968.18,2320.77 3968.18,2457.45 3937.08,2488.55 3786.54,2488.55 3755.91,2457.91 3755.91,2321.92 3780.57,2297.26
NetC3_1 on Top Layer 1 "NONET_L01_P-001" (solid, pour order 103): 2801.55,2495.61 2784.19,2478.24 2784.19,2407.14 2797.8,2393.54 2827.82,2393.54 2840.25,2381.12 2840.25,2233.36 2862.71,2210.9 3007.68,2210.9 3034.97,2238.19 3034.97,2449.06 2988.43,2495.6
PA_VBUS on Top Layer 1 "c" (solid, pour order 75): 2977.78,3478.63 2962,3494.41 2962,3510 2966.06,3514.06 3077.03,3514.06 3077.11,3514.13 3095.92,3514.13 3101.08,3508.97 3101.08,3477.16 3089.38,3465.39 3089.38,3408.34 3078.03,3396.98 3078.03,3334.46 3130.26,3282.22 3208.95,3282.22 3228.14,3263.03 3228.14,3190.04 3214.13,3176.02 2996.03,3176.02 2967.71,3204.35 2967.71,3357.22 2967.82,3357.33 2967.82,3404.07 2977.78,3413.92
NetC21_1 on Top Layer 1 "NONET_L01_P-001" (solid, pour order 158): 3805.14,3077.19 3805.13,3163.67 3818.51,3177.05 4074.58,3177.05 4104.97,3146.66 4104.97,3080.11 4081.3,3056.44 3825.88,3056.44
NetC43_1 on Top Layer 1 "c" (solid, pour order 108): 3396.4,2835.06 3373.18,2811.84 3347.2,2811.84 3303.59,2811.84 3269.22,2846.21 3269.22,2974.5 3160.61,3083.1 3160.61,3146.36 3180.56,3166.31 3368.7,3166.31 3396.4,3138.65
BATGND on Top Layer 1 "NONET_L01_P-001" (solid, pour order 104): 2836.76,2172.04 2836.76,1810.35 2809.5,1783.09 2611.09,1783.09 2583.41,1810.77 2583.41,2163.35 2609.52,2189.45 2819.35,2189.45
VBAT on Top Layer 1 "NONET_L01_P-001" (solid, pour order 87): 3051.85,1995.72 3078.8,1968.77 3078.8,1814.06 3052.43,1787.7 2871.72,1787.7 2848.38,1811.03 2848.38,1971.19 2872.89,1995.72
GND on Layer 5 "NONET_L01_P-001" (solid, remove dead copper, pour order 198): 3082,2209 3091,2200 3091,1819.39 3124.46,1785.93 4256.79,1785.93 4304.44,1833.57 4304.44,3472.11 4257.91,3518.63 2663.23,3518.63 2585.69,3441.09 2585.69,2232.99 2609.5,2209
BATGND on Layer 5 "NONET_L01_P-001" (solid, pour order 179): 2587.54,2149.75 2621.75,2183.98 3044.84,2183.98 3072.8,2156.02 3072.8,1811.59 3045.74,1784.53 2613.53,1784.53 2587.54,1810.52
AGND on Layer 5 "NONET_L01_P-001" (solid, pour order 146): 3163.4,2133.86 3101.25,2071.71 3101.25,2014.63 3124.04,1991.84 3712.44,1991.84 3737.59,2016.98 3737.59,2068.84 3672.57,2133.86
AGND1 on Layer 5 "NONET_L01_P-001" (solid, pour order 114): 3426.55,2633.86 3446.23,2614.17 3629.1,2614.17 3644.85,2629.92 3948.67,2629.92 3963.97,2645.21 3963.97,3114.19 3919.05,3159.11 3658.05,3159.11 3641.12,3142.18 3641.12,2831.57 3565.43,2755.88 3440.48,2755.88 3426.55,2742.19
PB_VBUS on Layer 5 "NONET_L01_P-001" (solid, pour order 178): 3738.58,3520.69 3909.58,3520.69 3940.61,3489.67 3940.61,3248.85 3909.05,3217.29 3738.02,3217.29 3708.48,3246.83 3708.48,3490.59
PA_VBUS on Layer 5 "NONET_L01_P-001" (solid, pour order 161): 2960.12,3519.79 3104.79,3519.79 3145.58,3478.99 3145.58,3231.56 3111.63,3197.61 2950.07,3197.61 2913.45,3234.22 2913.45,3473.12
GND on Layer 4 "NONET_L01_P-001" (solid, remove dead copper, pour order 200): 3065,2209 3091,2183 3091,1819.39 3124.46,1785.93 4256.79,1785.93 4304.44,1833.57 4304.44,3472.11 4257.91,3518.63 2663.23,3518.63 2585.69,3441.09 2585.69,2232.99 2609.5,2209
NetC21_1 on Layer 4 "NONET_L01_P-001" (solid, pour order 105): 3992,3154 4015.3,3177.3 4069.74,3177.3 4126,3121.05 4126,2497.92 3978.12,2346 3873.58,2346 3858.92,2360.66 3858.92,2442.3 3881.54,2464.93 3963.18,2464.93 4035,2536.74 4035,3026 3992,3069
BATGND on Layer 4 "NONET_L01_P-001" (solid, pour order 180): 2588.63,2151.49 2622.85,2185.72 3028.28,2185.72 3070.03,2143.97 3070.03,1809.45 3046.84,1786.27 2614.63,1786.27 2588.63,1812.26
no net on Top Solder "NONET_L01_P-001" (solid): 3432.23,3106.26 3690.82,3106.26 3690.82,3063.89 3432.22,3063.89
no net on Top Solder "NONET_L01_P-001" (solid): 3177.16,2708.66 3132.4,2708.66 3132.4,2244.09 3177.17,2244.09
no net on Top Solder "NONET_L01_P-001" (solid): 4126,2259 4126,2621.56 4083.99,2621.56 4083.99,2259
no net on Top Solder "NONET_L01_P-001" (solid): 3526.87,1984.25 3748.72,1984.25 3748.72,1941.89 3526.87,1941.89
GND on Layer 3 "NONET_L01_P-001" (solid, remove dead copper, pour order 205): 3065,2209 3091,2183 3091,1819.39 3124.46,1785.93 4256.79,1785.93 4304.44,1833.57 4304.44,3472.11 4257.91,3518.63 2663.23,3518.63 2585.69,3441.09 2585.69,2232.99 2609.5,2209
BATGND on Layer 3 "NONET_L01_P-001" (solid, pour order 181): 2587.69,2150.64 2621.9,2184.86 3028.14,2184.86 3072.95,2140.05 3072.95,1812.47 3045.89,1785.41 2613.68,1785.41 2587.69,1811.41
GND on Layer 2 "NONET_L01_P-001" (solid, remove dead copper, pour order 199): 3064,2209 3091,2182 3091,1819.39 3124.46,1785.93 4256.79,1785.93 4304.44,1833.57 4304.44,3472.11 4257.91,3518.63 2663.23,3518.63 2585.69,3441.09 2585.69,2232.99 2609.5,2209
BATGND on Layer 2 "NONET_L01_P-001" (solid, pour order 182): 2587.29,2151.08 2621.5,2185.31 3025.69,2185.31 3072.55,2138.45 3072.55,1812.91 3045.49,1785.86 2613.28,1785.86 2587.29,1811.85

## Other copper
Top Layer 1:
  pour cut-out: 3570,2327.62 3620,2327.62 3620,2264 3570,2264
  pour cut-out: 3197,2323.62 3247,2323.62 3247,2260 3197,2260
  pour cut-out: 3486.45,2033.05 3468.41,2033.05 3468.18,2033.28 3468.18,2006.05 3487.1,2006.05
  pour cut-out: 3946.77,2757.12 3993.23,2757.12 3993.23,2693.5 3946.77,2693.5
  pour cut-out: 3946.77,2998.62 3978,2998.62 3978,2935 3946.77,2935
  pour cut-out: 3430.35,2111.83 3458,2139.48 3458,2353.3 3365,2353.3 3365,2133.19 3386.36,2111.83
  pour cut-out: 3570.49,3522.55 3537,3489.07 3537,3435.98 3512.23,3411.39 3362.87,3411.39 3361.97,3410.48 3331.93,3440.52 3331.93,3492.5 3301.89,3522.55
  pour cut-out: 3325.51,2033.05 3343.55,2033.05 3343.78,2033.28 3343.78,2006.05 3324.86,2006.05
  pour cut-out: 3023.75,2545.66 3041.79,2563.7 3041.79,2451.62 3023.75,2469.65 2995.99,2497.41 2801.07,2497.41 2797.47,2501.01 2797.47,2545.66 2989.95,2545.66
  pour cut-out: 3855.65,2867.31 3839.65,2883.31 3614.18,2883.31 3614.18,2808 3725.66,2808 3840.34,2808 3855.65,2823.31
Layer 5:
  pour cut-out: 3570.49,3522.55 3537,3489.07 3537,3435.98 3512.23,3411.39 3362.87,3411.39 3361.97,3410.48 3331.93,3440.52 3331.93,3492.5 3301.89,3522.55
Layer 2:
  pour cut-out: 3570.49,3522.55 3537,3489.07 3537,3435.98 3512.23,3411.39 3362.87,3411.39 3361.97,3410.48 3331.93,3440.52 3331.93,3492.5 3301.89,3522.55
Layer 3:
  pour cut-out: 3570.49,3522.55 3537,3489.07 3537,3435.98 3512.23,3411.39 3362.87,3411.39 3361.97,3410.48 3331.93,3440.52 3331.93,3492.5 3301.89,3522.55
Layer 4:
  pour cut-out: 3570.49,3522.55 3537,3489.07 3537,3435.98 3512.23,3411.39 3362.87,3411.39 3361.97,3410.48 3331.93,3440.52 3331.93,3492.5 3301.89,3522.55
Bottom Layer:
  pour cut-out: 3750.79,2612.01 3751.78,2613 3796,2613 3796,2600.86 3797.25,2599.61 3750.79,2599.61
  pour cut-out: 3302.44,3508.58 3287.92,3523.11 3302.44,3523.11 3571.04,3523.11 3537.56,3489.62 3537.56,3436.54 3512.79,3411.95 3340.02,3411.95 3302.44,3449.53
  pour cut-out: 3296.13,2774.84 3296.13,2712.4 3296.13,2657.94 3242.8,2657.94 3242.8,2774.84
  pour cut-out: 3141.9,2472.31 3136.16,2478.05 3136.16,2472.31 3129.38,2472.31 3129.38,2326.26 3156.55,2326.26 3156.55,2445.22 3169.1,2457.77 3169.1,2466.42 3147.79,2466.42

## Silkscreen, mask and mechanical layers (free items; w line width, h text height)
Top Overlay:
  lines w10: 3156.43,1964.57 3156.43,3085.59 4103.93,3085.59 4103.93,1964.57 3156.43,1964.57
  text "GND" at 2603.89,1939.95 h40
  text "PMP41092" at 4125.89,1823.36 h40
  text "VBAT" at 3079.69,1768.67 h40
Mechanical 1:
  lines w10: 2559.06,3543.31 2559.06,1771.65 4330.71,1771.65 4330.71,3543.31 ; 2560.21,3542.03 4331.87,3542.03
